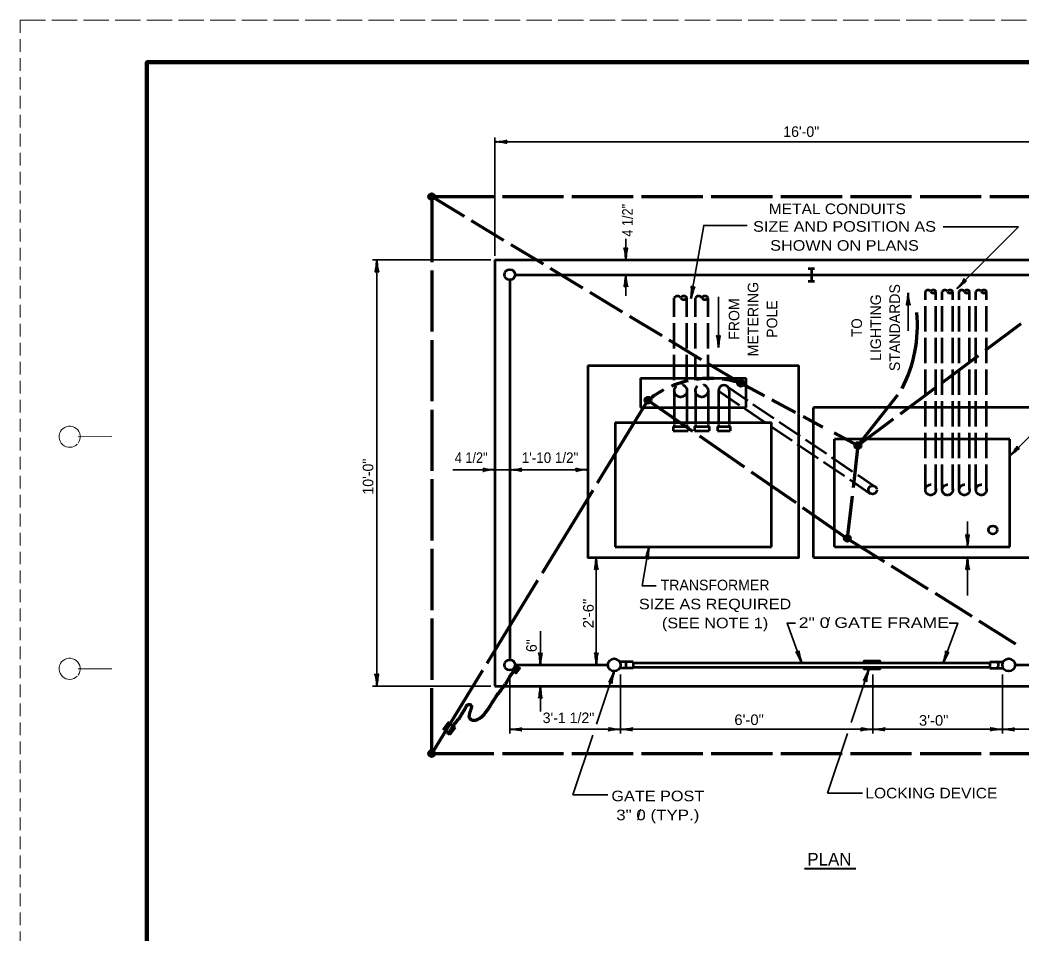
# Model space of a CAD drawing. Extents: x -1 to 679, y 0 to 440.
# Drawn here: x -1.5 to 236, y 223.4 to 440 of the extents above; entities that cross this region are included whole.
import ezdxf
from ezdxf.enums import TextEntityAlignment as Align

# ---------------------------------------------------------------- set-up
doc = ezdxf.new("R2010")
doc.units = 0
doc.linetypes.add('LONG_DASHED', pattern=[7.5, 6, -1.5])
doc.linetypes.add('MEDIUM_DASHED', pattern=[4.5, 3, -1.5])
doc.layers.add('1', color=7, linetype='Continuous', lineweight=53)
doc.layers.add('61', color=7, linetype='Continuous', lineweight=35)

msp = doc.modelspace()

# ---------------------------------------------------------------- hatches: boundary and pattern name
at = {"layer": '1'}
for points in [[(96.832, 398.11, 1), (95.332, 398.11, 1)], [(170.082, 353.86, 1), (168.582, 353.86, 1)], [(148.082, 349.86, 1), (146.582, 349.86, 1)], [(197.832, 339.11, 1), (196.332, 339.11, 1)], [(195.332, 317.11, 1), (193.832, 317.11, 1)], [(96.832, 266.11, 1), (95.332, 266.11, 1)]]:
    msp.add_hatch(color=256, dxfattribs=at).paths.add_polyline_path(points)

# ---------------------------------------------------------------- linework, layer by layer
at = {"layer": '1', "linetype": 'MEDIUM_DASHED', "lineweight": 13}
msp.add_line((-1.431, 439.961), (-1.491, -0.079), dxfattribs=at)
at = {"layer": '1', "lineweight": 35}
for p, q in [((111.082, 384.11), (111.082, 412.11)), ((111.082, 411.11), (261.082, 411.11)), ((142.082, 383.11), (142.082, 388.11)), ((110.082, 383.11), (82.082, 383.11)), ((83.082, 383.11), (83.082, 282.11)), ((142.082, 379.61), (142.082, 374.61)), ((209.006, 366.292), (209.006, 375.292)), ((164.049, 362.329), (164.049, 374.329)), ((111.082, 333.36), (101.082, 333.36)), ((114.582, 333.36), (111.082, 333.36)), ((114.582, 333.36), (133.082, 333.36)), ((223.082, 315.11), (223.082, 321.11)), ((135.082, 312.61), (135.082, 287.11)), ((223.082, 312.61), (223.082, 303.61)), ((121.832, 287.11), (121.832, 295.11)), ((139.332, 285.61), (135.147, 273.075)), ((199.69, 286.018), (195.505, 273.482)), ((114.582, 284.86), (114.582, 270.86)), ((140.832, 284.86), (140.832, 270.86)), ((200.635, 284.86), (200.635, 270.86)), ((231.332, 284.86), (231.332, 270.86)), ((110.082, 282.11), (82.082, 282.11)), ((121.832, 282.11), (121.832, 276.11)), ((194.634, 270.875), (189.915, 256.737)), ((134.277, 270.467), (129.557, 256.33)), ((189.915, 256.737), (198.197, 256.737)), ((129.557, 256.33), (137.84, 256.33))]:
    msp.add_line(p, q, dxfattribs=at)
at = {"layer": '1', "lineweight": 70}
for p, q in [((96.082, 398.11), (110.832, 398.11)), ((96.082, 398.11), (96.082, 382.61)), ((96.082, 398.11), (103.741, 393.484)), ((112.832, 398.11), (127.332, 398.11)), ((129.332, 398.11), (143.832, 398.11)), ((145.832, 398.11), (160.332, 398.11)), ((162.332, 398.11), (176.832, 398.11)), ((178.832, 398.11), (193.332, 398.11)), ((195.332, 398.11), (209.832, 398.11)), ((211.832, 398.11), (226.332, 398.11)), ((228.332, 398.11), (242.832, 398.11)), ((105.453, 392.45), (113.111, 387.823)), ((114.823, 386.789), (122.481, 382.163)), ((96.082, 380.61), (96.082, 366.11)), ((124.193, 381.129), (131.851, 376.502)), ((133.563, 375.468), (141.221, 370.842)), ((142.934, 369.808), (150.592, 365.181)), ((227.308, 361.684), (235.781, 368.012)), ((96.082, 364.11), (96.082, 349.61)), ((152.304, 364.147), (159.962, 359.521)), ((217.233, 354.159), (225.706, 360.487)), ((161.674, 358.487), (169.332, 353.86)), ((169.332, 353.86), (174.945, 350.877)), ((207.158, 346.635), (215.63, 352.963)), ((147.332, 349.86), (135.303, 330.202)), ((147.332, 349.86), (157.912, 342.527)), ((176.711, 349.938), (182.324, 346.955)), ((197.082, 339.11), (206.582, 351.11)), ((96.082, 347.61), (96.082, 333.11)), ((184.09, 346.016), (188.82, 343.502)), ((197.082, 339.11), (205.555, 345.438)), ((191.469, 342.094), (197.082, 339.11)), ((159.556, 341.388), (170.135, 334.055)), ((197.082, 339.11), (195.945, 329.104)), ((171.779, 332.916), (182.359, 325.582)), ((96.082, 331.11), (96.082, 316.61)), ((134.259, 328.496), (122.229, 308.838)), ((195.719, 327.117), (194.582, 317.11)), ((184.003, 324.443), (194.582, 317.11)), ((194.582, 317.11), (203.286, 311.663)), ((96.082, 314.61), (96.082, 300.11)), ((204.982, 310.603), (213.686, 305.156)), ((121.185, 307.132), (109.156, 287.474)), ((215.381, 304.095), (224.085, 298.648)), ((96.082, 298.11), (96.082, 283.61)), ((225.781, 297.587), (234.485, 292.141)), ((108.112, 285.768), (96.082, 266.11)), ((96.082, 266.11), (96.082, 281.61)), ((96.082, 266.11), (110.832, 266.11)), ((112.832, 266.11), (127.332, 266.11)), ((129.332, 266.11), (143.832, 266.11)), ((145.832, 266.11), (160.332, 266.11)), ((162.332, 266.11), (176.832, 266.11)), ((178.832, 266.11), (193.332, 266.11)), ((195.332, 266.11), (209.832, 266.11)), ((211.832, 266.11), (226.332, 266.11)), ((228.332, 266.11), (242.832, 266.11))]:
    msp.add_line(p, q, dxfattribs=at)
at = {"layer": '1'}
for p, q in [((111.082, 383.11), (261.082, 383.11)), ((111.082, 383.11), (111.082, 282.11)), ((185.332, 381.11), (186.832, 381.11)), ((186.082, 381.11), (186.082, 378.11)), ((114.582, 378.36), (114.582, 288.36)), ((115.832, 379.61), (256.332, 379.61)), ((185.332, 378.11), (186.832, 378.11)), ((133.082, 358.11), (183.082, 358.11)), ((145.582, 355.11), (170.582, 355.11)), ((145.582, 355.11), (145.582, 348.11)), ((170.582, 348.11), (170.582, 355.11)), ((153.582, 352.11), (153.582, 344.61)), ((156.582, 352.11), (156.582, 344.61)), ((158.582, 352.11), (158.582, 344.61)), ((161.582, 352.11), (161.582, 344.61)), ((164.082, 352.11), (164.082, 344.61)), ((166.582, 352.11), (166.582, 344.61)), ((145.582, 348.11), (170.582, 348.11)), ((186.582, 312.61), (186.582, 348.11)), ((139.582, 344.61), (176.582, 344.61)), ((139.582, 344.61), (139.582, 315.11)), ((176.582, 315.11), (176.582, 344.61)), ((153.582, 344.11), (153.582, 343.61)), ((156.582, 344.11), (156.582, 343.61)), ((158.582, 344.11), (158.582, 343.61)), ((161.582, 344.11), (161.582, 343.61)), ((164.082, 344.11), (164.082, 343.61)), ((166.582, 344.11), (166.582, 343.61)), ((233.082, 340.61), (191.582, 340.61)), ((191.582, 315.11), (191.582, 340.61)), ((233.082, 315.11), (233.082, 340.61)), ((139.582, 315.11), (176.582, 315.11)), ((191.582, 315.11), (233.082, 315.11)), ((143.832, 287.86), (140.631, 287.86)), ((142.082, 287.86), (142.082, 286.36)), ((143.832, 287.86), (143.832, 286.36)), ((228.332, 287.86), (228.332, 286.36)), ((228.332, 287.86), (231.533, 287.86)), ((115.832, 287.11), (137.832, 287.11)), ((143.832, 286.36), (140.631, 286.36)), ((228.332, 286.36), (231.533, 286.36)), ((234.332, 287.11), (256.332, 287.11)), ((111.082, 282.11), (261.082, 282.11))]:
    msp.add_line(p, q, dxfattribs=at)
at = {"layer": '1', "linetype": 'LONG_DASHED'}
for p, q in [((213.082, 328.61), (213.082, 375.61)), ((215.582, 328.61), (215.582, 375.61)), ((217.082, 328.61), (217.082, 375.61)), ((219.582, 328.61), (219.582, 375.61)), ((221.082, 328.61), (221.082, 375.61)), ((223.582, 328.61), (223.582, 375.61)), ((225.082, 328.61), (225.082, 375.61)), ((227.582, 328.61), (227.582, 375.61)), ((153.582, 354.61), (153.582, 374.11)), ((156.582, 354.61), (156.582, 374.11)), ((158.582, 354.61), (158.582, 374.11)), ((161.582, 354.61), (161.582, 374.11)), ((164.082, 352.066), (200.249, 327.616)), ((166.014, 353.155), (201.36, 329.259)), ((153.332, 343.61), (156.832, 343.61)), ((153.332, 343.61), (153.332, 342.61)), ((153.332, 342.61), (156.832, 342.61)), ((156.832, 343.61), (156.832, 342.61)), ((158.332, 343.61), (161.832, 343.61)), ((158.332, 343.61), (158.332, 342.61)), ((158.332, 342.61), (161.832, 342.61)), ((161.832, 343.61), (161.832, 342.61)), ((163.832, 343.61), (166.832, 343.61)), ((163.832, 343.61), (163.832, 342.61)), ((163.832, 342.61), (166.832, 342.61)), ((166.832, 343.61), (166.832, 342.61))]:
    msp.add_line(p, q, dxfattribs=at)
at = {"layer": '1', "lineweight": 40}
msp.add_line((184.417, 238.861), (196.632, 238.861), dxfattribs=at)
at = {"layer": '1', "lineweight": 35}
for points in [[(157.526, 373.971), (160.578, 391.28), (170.865, 391.28)], [(220.562, 376.332), (235.158, 390.927), (217.342, 390.927)], [(233.082, 336.61), (245.81, 349.338), (283.703, 349.338)], [(147.582, 315.11), (145.958, 305.896), (149.245, 305.896)], [(183.738, 287.61), (180.318, 297.007), (182.318, 297.007)], [(217.332, 287.61), (220.752, 297.007), (218.752, 297.007)], [(114.582, 271.86), (140.832, 271.86), (200.635, 271.86), (231.332, 271.86), (257.582, 271.86)]]:
    msp.add_lwpolyline(points, dxfattribs=at)
at = {"layer": '1'}
for points in [[(133.082, 358.11), (133.082, 312.61), (183.082, 312.61), (183.082, 358.11)], [(186.582, 312.61), (238.082, 312.61), (238.082, 348.11), (186.582, 348.11)], [(143.832, 287.61), (202.332, 287.61), (228.332, 287.61)], [(143.832, 286.61), (202.332, 286.61), (228.332, 286.61)]]:
    msp.add_lwpolyline(points, dxfattribs=at)
for points in [[(198.582, 287.61), (198.582, 288.11), (202.332, 288.11), (202.332, 287.61)], [(116.932, 286.366), (116.013, 285.181), (115.223, 285.794), (116.142, 286.979), (116.932, 286.367)], [(198.582, 286.61), (202.332, 286.61), (202.332, 286.11), (198.582, 286.11)], [(101.663, 272.251), (100.438, 270.671), (98.857, 271.897), (100.083, 273.477)]]:
    msp.add_lwpolyline(points, close=True, dxfattribs=at)
for centre, radius in [((96.082, 398.11), 0.75), ((114.582, 379.61), 1.25), ((169.332, 353.86), 0.75), ((147.332, 349.86), 0.75), ((197.082, 339.11), 0.75), ((229.082, 319.11), 1), ((194.582, 317.11), 0.75), ((114.582, 287.11), 1.25), ((139.332, 287.11), 1.5), ((232.832, 287.11), 1.5), ((96.082, 266.11), 0.75)]:
    msp.add_circle(centre, radius, dxfattribs=at)
at = {"layer": '1', "linetype": 'LONG_DASHED'}
for centre, radius in [((155.082, 352.11), 1.5), ((160.082, 352.11), 1.5), ((200.582, 328.61), 1), ((214.332, 328.61), 1.25), ((218.332, 328.61), 1.25), ((222.332, 328.61), 1.25), ((226.332, 328.61), 1.25)]:
    msp.add_circle(centre, radius, dxfattribs=at)
at = {"layer": '1'}
for centre, radius, start, end in [((213.707, 375.256), 0.719, 29.57629, 150.42371), ((214.957, 375.256), 0.719, 29.57629, 150.42371), ((214.957, 375.965), 0.719, 209.57629, 330.42371), ((217.707, 375.256), 0.719, 29.57629, 150.42371), ((218.957, 375.256), 0.719, 29.57629, 150.42371), ((218.957, 375.965), 0.719, 209.57629, 330.42371), ((221.707, 375.256), 0.719, 29.57629, 150.42371), ((222.957, 375.256), 0.719, 29.57629, 150.42371), ((222.957, 375.965), 0.719, 209.57629, 330.42371), ((225.707, 375.256), 0.719, 29.57629, 150.42371), ((226.957, 375.256), 0.719, 29.57629, 150.42371), ((226.957, 375.965), 0.719, 209.57629, 330.42371), ((154.332, 373.621), 0.895, 33.11864, 146.88135), ((155.832, 373.621), 0.895, 33.11864, 146.88135), ((155.832, 374.6), 0.895, 213.11865, 326.88136), ((159.332, 373.621), 0.895, 33.11864, 146.88135), ((160.832, 373.621), 0.895, 33.11864, 146.88135), ((160.832, 374.6), 0.895, 213.11865, 326.88136), ((165.332, 352.175), 1.252, 357.01919, 182.98081), ((229.653, 287.11), 0.771, 283.46774, 76.53226)]:
    msp.add_arc(centre, radius, start, end, dxfattribs=at)
at = {"layer": '1', "lineweight": 70}
for centre, radius, start, end in [((178.142, 367.675), 33.071, 332.90084, 5.09207), ((162.018, 331.592), 23.439, 102.75016, 112.84762), ((162.018, 331.592), 23.439, 87.76241, 97.85974), ((162.018, 331.592), 23.439, 71.81547, 82.6976), ((162.018, 331.592), 23.439, 117.91242, 128.79422)]:
    msp.add_arc(centre, radius, start, end, dxfattribs=at)
at = {"layer": '1', "lineweight": 40}
for centre, major_axis, ratio, start_param, end_param in [((112.203, 410.899), (1.756, -0.176), 0.07063, 6.2823074, 8.5597026), ((112.203, 410.899), (1.756, -0.176), 0.07063, 6.2823074, 8.5597026), ((112.174, 411.387), (-1.786, -0.156), 0.122415, 0.8963533, 3.1415927), ((112.174, 411.387), (-1.786, -0.156), 0.122415, 0.8963533, 3.1415927), ((141.806, 384.201), (0.156, -1.786), 0.122415, 0.8963533, 3.1415927), ((141.806, 384.201), (0.156, -1.786), 0.122415, 0.8963533, 3.1415927), ((142.294, 384.231), (0.176, 1.756), 0.07063, 6.2823074, 8.5597026), ((142.294, 384.231), (0.176, 1.756), 0.07063, 6.2823074, 8.5597026), ((82.871, 381.99), (-0.176, -1.756), 0.07063, 6.2823074, 8.5597026), ((82.871, 381.99), (-0.176, -1.756), 0.07063, 6.2823074, 8.5597026), ((83.359, 382.019), (-0.156, 1.786), 0.122415, 0.8963533, 3.1415927), ((83.359, 382.019), (-0.156, 1.786), 0.122415, 0.8963533, 3.1415927), ((141.871, 378.49), (-0.176, -1.756), 0.07063, 6.2823074, 8.5597026), ((142.359, 378.519), (-0.156, 1.786), 0.122415, 0.8963533, 3.1415927), ((221.139, 377.299), (-1.152, -1.373), 0.122415, 0.8963533, 3.1415927), ((221.504, 376.975), (1.366, 1.118), 0.07063, 6.2823074, 8.5597026), ((157.443, 375.094), (-0.156, -1.786), 0.122415, 0.8963533, 3.1415927), ((157.443, 375.094), (-0.156, -1.786), 0.122415, 0.8963533, 3.1415927), ((157.929, 375.038), (0.478, 1.699), 0.07063, 6.2823074, 8.5597026), ((157.929, 375.038), (0.478, 1.699), 0.07063, 6.2823074, 8.5597026), ((208.795, 374.171), (0.176, 1.756), 0.07063, 3.1407148, 5.41811), ((208.795, 374.171), (0.176, 1.756), 0.07063, 3.1407148, 5.41811), ((209.283, 374.2), (-0.156, 1.786), 0.122415, 0.8963533, 3.1415927), ((209.283, 374.2), (-0.156, 1.786), 0.122415, 0.8963533, 3.1415927), ((163.773, 363.42), (0.156, -1.786), 0.122415, 0.8963533, 3.1415927), ((163.773, 363.42), (0.156, -1.786), 0.122415, 0.8963533, 3.1415927), ((164.261, 363.45), (-0.176, -1.756), 0.07063, 3.1407148, 5.41811), ((164.261, 363.45), (-0.176, -1.756), 0.07063, 3.1407148, 5.41811), ((233.659, 337.577), (-1.152, -1.373), 0.122415, 0.8963533, 3.1415927), ((233.659, 337.577), (-1.152, -1.373), 0.122415, 0.8963533, 3.1415927), ((234.024, 337.253), (1.366, 1.118), 0.07063, 6.2823074, 8.5597026), ((234.024, 337.253), (1.366, 1.118), 0.07063, 6.2823074, 8.5597026), ((109.991, 333.084), (1.786, 0.156), 0.122415, 0.8963533, 3.1415927), ((109.991, 333.084), (1.786, 0.156), 0.122415, 0.8963533, 3.1415927), ((109.962, 333.572), (1.756, -0.176), 0.07063, 3.1407148, 5.41811), ((109.962, 333.572), (1.756, -0.176), 0.07063, 3.1407148, 5.41811), ((115.703, 333.149), (-1.756, 0.176), 0.07063, 3.1407148, 5.41811), ((115.703, 333.149), (-1.756, 0.176), 0.07063, 3.1407148, 5.41811), ((115.674, 333.637), (-1.786, -0.156), 0.122415, 0.8963533, 3.1415927), ((115.674, 333.637), (-1.786, -0.156), 0.122415, 0.8963533, 3.1415927), ((131.991, 333.084), (1.786, 0.156), 0.122415, 0.8963533, 3.1415927), ((131.962, 333.572), (1.756, -0.176), 0.07063, 3.1407148, 5.41811), ((222.806, 316.201), (0.156, -1.786), 0.122415, 0.8963533, 3.1415927), ((222.806, 316.201), (0.156, -1.786), 0.122415, 0.8963533, 3.1415927), ((223.294, 316.231), (-0.176, -1.756), 0.07063, 3.1407148, 5.41811), ((223.294, 316.231), (-0.176, -1.756), 0.07063, 3.1407148, 5.41811), ((147.179, 314.044), (-0.478, -1.699), 0.07063, 6.2823074, 8.5597026), ((147.665, 313.988), (0.156, 1.786), 0.122415, 0.8963533, 3.1415927), ((134.871, 311.49), (0.176, 1.756), 0.07063, 3.1407148, 5.41811), ((134.871, 311.49), (0.176, 1.756), 0.07063, 3.1407148, 5.41811), ((135.359, 311.519), (-0.156, 1.786), 0.122415, 0.8963533, 3.1415927), ((135.359, 311.519), (-0.156, 1.786), 0.122415, 0.8963533, 3.1415927), ((222.871, 311.49), (0.176, 1.756), 0.07063, 3.1407148, 5.41811), ((223.359, 311.519), (-0.156, 1.786), 0.122415, 0.8963533, 3.1415927), ((121.556, 288.201), (0.156, -1.786), 0.122415, 0.8963533, 3.1415927), ((122.044, 288.231), (-0.176, -1.756), 0.07063, 3.1407148, 5.41811), ((134.806, 288.201), (0.156, -1.786), 0.122415, 0.8963533, 3.1415927), ((135.294, 288.231), (-0.176, -1.756), 0.07063, 3.1407148, 5.41811), ((183.105, 288.541), (0.757, -1.625), 0.122415, 0.8963533, 3.1415927), ((183.105, 288.541), (0.757, -1.625), 0.122415, 0.8963533, 3.1415927), ((183.553, 288.736), (-0.436, 1.711), 0.07063, 6.2823074, 8.5597026), ((183.553, 288.736), (-0.436, 1.711), 0.07063, 6.2823074, 8.5597026), ((217.446, 288.73), (-0.464, -1.731), 0.122415, 0.8963533, 3.1415927), ((217.914, 288.591), (0.766, 1.59), 0.07063, 6.2823074, 8.5597026), ((82.806, 283.201), (0.156, -1.786), 0.122415, 0.8963533, 3.1415927), ((83.294, 283.231), (0.176, 1.756), 0.07063, 6.2823074, 8.5597026), ((138.777, 284.614), (-0.723, -1.61), 0.07063, 6.2823074, 8.5597026), ((139.249, 284.488), (0.417, 1.743), 0.122415, 0.8963533, 3.1415927), ((199.134, 285.022), (-0.723, -1.61), 0.07063, 6.2823074, 8.5597026), ((199.606, 284.895), (0.417, 1.743), 0.122415, 0.8963533, 3.1415927), ((121.621, 280.99), (0.176, 1.756), 0.07063, 3.1407148, 5.41811), ((122.109, 281.019), (-0.156, 1.786), 0.122415, 0.8963533, 3.1415927), ((115.703, 271.649), (-1.756, 0.176), 0.07063, 3.1407148, 5.41811), ((115.674, 272.137), (-1.786, -0.156), 0.122415, 0.8963533, 3.1415927), ((139.741, 271.584), (1.786, 0.156), 0.122415, 0.8963533, 3.1415927), ((139.741, 271.584), (1.786, 0.156), 0.122415, 0.8963533, 3.1415927), ((139.712, 272.072), (1.756, -0.176), 0.07063, 3.1407148, 5.41811), ((139.712, 272.072), (1.756, -0.176), 0.07063, 3.1407148, 5.41811), ((141.953, 271.649), (-1.756, 0.176), 0.07063, 3.1407148, 5.41811), ((141.953, 271.649), (-1.756, 0.176), 0.07063, 3.1407148, 5.41811), ((141.924, 272.137), (-1.786, -0.156), 0.122415, 0.8963533, 3.1415927), ((141.924, 272.137), (-1.786, -0.156), 0.122415, 0.8963533, 3.1415927), ((199.543, 271.584), (1.786, 0.156), 0.122415, 0.8963533, 3.1415927), ((199.543, 271.584), (1.786, 0.156), 0.122415, 0.8963533, 3.1415927), ((199.514, 272.072), (1.756, -0.176), 0.07063, 3.1407148, 5.41811), ((199.514, 272.072), (1.756, -0.176), 0.07063, 3.1407148, 5.41811), ((201.755, 271.649), (-1.756, 0.176), 0.07063, 3.1407148, 5.41811), ((201.755, 271.649), (-1.756, 0.176), 0.07063, 3.1407148, 5.41811), ((201.726, 272.137), (-1.786, -0.156), 0.122415, 0.8963533, 3.1415927), ((201.726, 272.137), (-1.786, -0.156), 0.122415, 0.8963533, 3.1415927), ((230.241, 271.584), (1.786, 0.156), 0.122415, 0.8963533, 3.1415927), ((230.241, 271.584), (1.786, 0.156), 0.122415, 0.8963533, 3.1415927), ((230.212, 272.072), (1.756, -0.176), 0.07063, 3.1407148, 5.41811), ((230.212, 272.072), (1.756, -0.176), 0.07063, 3.1407148, 5.41811), ((232.453, 271.649), (-1.756, 0.176), 0.07063, 3.1407148, 5.41811), ((232.453, 271.649), (-1.756, 0.176), 0.07063, 3.1407148, 5.41811), ((232.424, 272.137), (-1.786, -0.156), 0.122415, 0.8963533, 3.1415927), ((232.424, 272.137), (-1.786, -0.156), 0.122415, 0.8963533, 3.1415927)]:
    msp.add_ellipse(centre, major_axis=major_axis, ratio=ratio, start_param=start_param, end_param=end_param, dxfattribs=at)
at = {"layer": '1', "lineweight": 70}
for points in [[(116.618, 286.778), (116.512, 286.544), (116.407, 286.336), (116.302, 286.181), (116.171, 286.051), (115.987, 285.87), (115.83, 285.714), (115.699, 285.611), (115.516, 285.482), (115.332, 285.327), (115.149, 285.145), (115.018, 284.964), (114.86, 284.808), (114.729, 284.548), (114.624, 284.419), (114.518, 284.263), (114.439, 284.107), (114.281, 283.847), (114.149, 283.562), (113.992, 283.302), (113.86, 283.12), (113.702, 282.861), (113.518, 282.549), (113.308, 282.29), (113.072, 281.978), (112.888, 281.719), (112.783, 281.589), (112.677, 281.433), (112.494, 281.226), (112.389, 281.096), (112.31, 280.914), (112.126, 280.707), (112.021, 280.551), (111.89, 280.37), (111.784, 280.24), (111.627, 280.085), (111.522, 279.929), (111.364, 279.695), (111.259, 279.54), (111.102, 279.358), (110.996, 279.15), (110.865, 278.943), (110.707, 278.683), (110.575, 278.475), (110.444, 278.242), (110.286, 278.06), (110.155, 277.826), (110.023, 277.567), (109.917, 277.385), (109.812, 277.203), (109.655, 276.995), (109.549, 276.814), (109.444, 276.658), (109.396, 276.586)], [(105.486, 277.491), (105.418, 277.547), (105.247, 277.654), (105.076, 277.675), (104.905, 277.697), (104.713, 277.675), (104.521, 277.59), (104.371, 277.483), (104.2, 277.184), (104.093, 276.97), (103.965, 276.734), (103.837, 276.478), (103.687, 276.285), (103.601, 276.136), (103.452, 275.922), (103.345, 275.751), (103.195, 275.516), (103.088, 275.302), (103.003, 275.109), (102.832, 274.831), (102.682, 274.617), (102.575, 274.446), (102.383, 274.233), (102.233, 274.019), (102.062, 273.848), (101.849, 273.634), (101.699, 273.42), (101.507, 273.206), (101.336, 272.971), (101.25, 272.821), (101.122, 272.607), (101.015, 272.436), (100.929, 272.265), (100.801, 272.051), (100.673, 271.859), (100.502, 271.602), (100.352, 271.367), (100.203, 271.174), (100.032, 270.939), (99.903, 270.768), (99.841, 270.657)], [(105.486, 277.491), (105.495, 277.32), (105.522, 277.147), (105.468, 276.968), (105.415, 276.775), (105.349, 276.57), (105.283, 276.357), (105.203, 276.138), (105.143, 275.972), (105.077, 275.779), (105.024, 275.593), (104.984, 275.421), (104.964, 275.235), (104.971, 275.049), (104.976, 274.995)], [(109.621, 276.89), (109.534, 276.783), (109.376, 276.575), (109.245, 276.42), (109.114, 276.264), (108.956, 276.083), (108.799, 275.875), (108.694, 275.719), (108.562, 275.538), (108.405, 275.278), (108.299, 275.123), (108.168, 275.019), (108.037, 274.916), (107.854, 274.76), (107.697, 274.631), (107.566, 274.527), (107.278, 274.347), (107.069, 274.244), (106.86, 274.115), (106.677, 274.037), (106.442, 273.961), (106.207, 273.936), (105.999, 273.937), (105.764, 273.964), (105.504, 274.07), (105.245, 274.254), (105.115, 274.463), (105.012, 274.62), (104.987, 274.855), (104.976, 274.995)]]:
    msp.add_spline(points, degree=3, dxfattribs=at)
at = {"layer": '61', "linetype": 'LONG_DASHED', "lineweight": 13}
msp.add_line((-1.431, 439.961), (678.589, 439.961), dxfattribs=at)
at = {"layer": '61', "lineweight": 13}
for p, q in [((12.289, 341.201), (20.269, 341.221)), ((12.269, 286.201), (20.269, 286.201))]:
    msp.add_line(p, q, dxfattribs=at)
at = {"layer": '61', "lineweight": 158}
msp.add_lwpolyline([(667.609, 429.961), (28.569, 429.961), (28.569, 9.941)], dxfattribs=at)
at = {"layer": '61', "lineweight": 13}
for centre, end in [((10.267, 341.202), 316.23216), ((10.267, 286.202), 315.37577)]:
    msp.add_arc(centre, 2.5, 323.13009, end, dxfattribs=at)

# ---------------------------------------------------------------- texts
at = {"layer": '1'}
for s, height, p in [('16\'-0"', 2.5, (179.408, 412.261)), ('/', 2.5, (189.573, 295.871)), ('3\'-1 1/2"', 2.5, (122.385, 273.335)), ('/', 2.5, (144.797, 250.361)), ('PLAN', 3, (185.1, 239.583))]:
    msp.add_text(s, height=height, dxfattribs=at).set_placement(p)
for s, width, p in [('4 1/2"', 0.9, (143.72, 388.626)), ('2\'-6"', 1.05, (134.46, 295.806))]:
    msp.add_text(s, height=2.5, rotation=90, dxfattribs=dict(at, width=width)).set_placement(p)
for s, width, p in [('METAL CONDUITS', 1.1, (175.978, 393.962)), ('4 1/2"', 0.9, (101.555, 334.983)), ('1\'-10 1/2"', 0.95, (117.434, 334.983)), ('1\'-10 1/2"', 0.95, (117.434, 334.983)), ('2" 0 GATE FRAME', 1.25, (183.07, 295.892)), ('6\'-0"', 1.05, (167.813, 272.878)), ('3\'-0"', 1.05, (211.563, 272.726)), ('LOCKING DEVICE', 1.1, (198.872, 255.493))]:
    msp.add_text(s, height=2.5, dxfattribs=dict(at, width=width)).set_placement(p)
for s, width, p in [('SIZE AND POSITION AS', 1.15, (193.927, 389.789)), ('SHOWN ON PLANS', 1.15, (193.927, 385.289)), ('SIZE AS REQUIRED', 1.15, (163.247, 300.307)), ('(SEE NOTE 1)', 1.15, (163.247, 295.807)), ('GATE POST', 1.15, (149.672, 254.816)), ('3" 0 (TYP.)', 1.2, (149.672, 250.316))]:
    msp.add_text(s, height=2.5, dxfattribs=dict(at, width=width)).set_placement(p, align=Align.CENTER)
for s, p in [('METERING', (173.49, 369.082)), ('STANDARDS', (207.072, 367.061)), ('FROM', (168.99, 369.082)), ('POLE', (177.99, 369.083)), ('LIGHTING', (202.572, 367.061))]:
    msp.add_text(s, height=2.5, rotation=90, dxfattribs=at).set_placement(p, align=Align.CENTER)
at = {"layer": '1', "width": 0.95}
msp.add_text('TO', height=2.5, rotation=90, dxfattribs=at).set_placement((198.072, 367.061), align=Align.CENTER)
at = {"layer": '1'}
for s, p in [('10\'-0"', (82.246, 327.49)), ('6"', (120.975, 290.16))]:
    msp.add_text(s, height=2.5, rotation=90, dxfattribs=at).set_placement(p)
msp.add_text('TRANSFORMER', height=2.5, dxfattribs=at).set_placement((163.247, 304.807), align=Align.CENTER)

doc.saveas('drawing.dxf')
